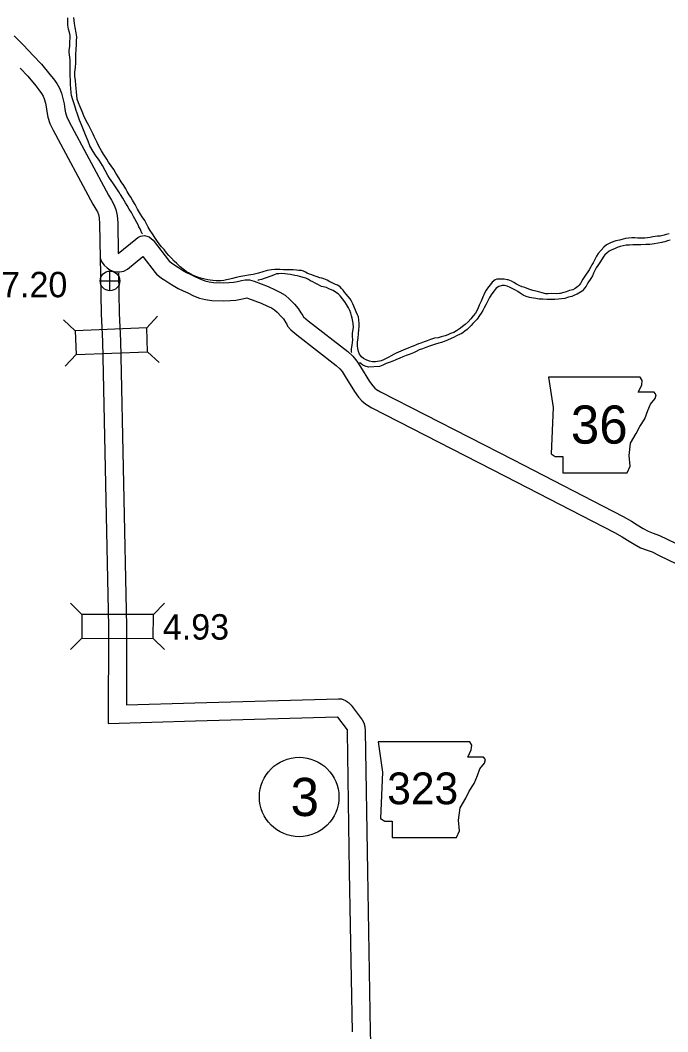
# Model space of a CAD drawing. Extents: x -939622 to -934222, y 1383701 to 1385301.
# Drawn here: x -936285.2 to -936253, y 1384484.4 to 1384534.8 of the extents above; entities that cross this region are included whole.
import ezdxf

# ---------------------------------------------------------------- set-up
doc = ezdxf.new("R2010")
doc.units = 0
for name, color, linetype in [('10', 7, 'Continuous'), ('20', 7, 'Continuous'), ('21', 7, 'Continuous'), ('25', 7, 'Continuous'), ('26', 7, 'Continuous'), ('27', 7, 'Continuous'), ('9', 7, 'Continuous')]:
    doc.layers.add(name, color=color, linetype=linetype)

msp = doc.modelspace()

# ---------------------------------------------------------------- linework, layer by layer
at = {"layer": '10'}
for points in [[(-936285.526, 1384534.038), (-936285.08, 1384533.582), (-936284.57, 1384533.041)], [(-936284.573, 1384533.044), (-936284.164, 1384532.618), (-936283.745, 1384532.106), (-936283.572, 1384531.883), (-936283.408, 1384531.657), (-936283.272, 1384531.427), (-936283.173, 1384531.173), (-936283.097, 1384530.903), (-936283.038, 1384530.648), (-936283.006, 1384530.383), (-936282.974, 1384530.194), (-936282.908, 1384529.999), (-936282.786, 1384529.739), (-936280.82, 1384526.086), (-936280.672, 1384525.843), (-936280.558, 1384525.629), (-936280.46, 1384525.374), (-936280.402, 1384525.086), (-936280.368, 1384524.714), (-936280.35, 1384523.196), (-936280.342, 1384523.189), (-936280.34, 1384523.188), (-936279.466, 1384523.908), (-936279.371, 1384523.99), (-936279.231, 1384524.05), (-936279.04, 1384524.085), (-936278.797, 1384524.018), (-936278.609, 1384523.847), (-936277.785, 1384522.789), (-936277.777, 1384522.777), (-936277.762, 1384522.765), (-936277.693, 1384522.722), (-936277.529, 1384522.612), (-936277.335, 1384522.486), (-936277.136, 1384522.359), (-936276.939, 1384522.243), (-936276.725, 1384522.141), (-936276.495, 1384522.03), (-936276.226, 1384521.904), (-936276.029, 1384521.825), (-936275.819, 1384521.775), (-936275.595, 1384521.742), (-936275.12, 1384521.73), (-936274.807, 1384521.739), (-936274.603, 1384521.758), (-936274.401, 1384521.79), (-936274.202, 1384521.835), (-936274.021, 1384521.875), (-936273.803, 1384521.869), (-936273.572, 1384521.802), (-936272.878, 1384521.543), (-936272.525, 1384521.379), (-936272.288, 1384521.267), (-936272.019, 1384521.106), (-936271.806, 1384520.911), (-936271.558, 1384520.664), (-936271.376, 1384520.451), (-936271.245, 1384520.234), (-936271.149, 1384520.105), (-936271.124, 1384520.043)], [(-936285.222, 1384532.421), (-936284.838, 1384532.021), (-936284.449, 1384531.544), (-936284.292, 1384531.343), (-936284.162, 1384531.163), (-936284.084, 1384531.031), (-936284.027, 1384530.887), (-936283.969, 1384530.68), (-936283.926, 1384530.491), (-936283.896, 1384530.253), (-936283.849, 1384529.974), (-936283.745, 1384529.664), (-936283.591, 1384529.335), (-936281.601, 1384525.638), (-936281.454, 1384525.396), (-936281.378, 1384525.254), (-936281.327, 1384525.122), (-936281.294, 1384524.956), (-936281.267, 1384524.667), (-936281.247, 1384522.946), (-936281.161, 1384522.755), (-936281.039, 1384522.597), (-936280.894, 1384522.478), (-936280.753, 1384522.375), (-936280.53, 1384522.271), (-936280.262, 1384522.265), (-936280.056, 1384522.31), (-936279.881, 1384522.401), (-936279.115, 1384523.031), (-936278.501, 1384522.243), (-936278.435, 1384522.154), (-936278.289, 1384522.033), (-936278.18, 1384521.965), (-936278.026, 1384521.862), (-936277.823, 1384521.729), (-936277.606, 1384521.591), (-936277.362, 1384521.448), (-936277.114, 1384521.329), (-936276.881, 1384521.218), (-936276.584, 1384521.078), (-936276.301, 1384520.965), (-936275.99, 1384520.891), (-936275.672, 1384520.844), (-936275.118, 1384520.83), (-936274.753, 1384520.84), (-936274.49, 1384520.865), (-936274.231, 1384520.906), (-936274.006, 1384520.957), (-936273.94, 1384520.971), (-936273.854, 1384520.947), (-936273.225, 1384520.712), (-936272.908, 1384520.565), (-936272.713, 1384520.472), (-936272.56, 1384520.381), (-936272.428, 1384520.26), (-936272.218, 1384520.051), (-936272.108, 1384519.923), (-936271.993, 1384519.732), (-936271.94, 1384519.66), (-936271.902, 1384519.566)], [(-936281.248, 1384523.036), (-936281.186, 1384520.184), (-936281.132, 1384518.802), (-936280.824, 1384504.606), (-936280.838, 1384499.779), (-936276.499, 1384499.898), (-936269.427, 1384500.095), (-936269.426, 1384500.094), (-936268.941, 1384499.459), (-936268.939, 1384499.455), (-936268.931, 1384499.358), (-936268.831, 1384492.386), (-936268.688, 1384484.416)], [(-936280.33, 1384522.202), (-936280.287, 1384520.211), (-936280.233, 1384518.829), (-936279.924, 1384504.615), (-936279.935, 1384500.704), (-936276.524, 1384500.797), (-936269.369, 1384500.997), (-936269.225, 1384500.994), (-936269.021, 1384500.924), (-936268.865, 1384500.81), (-936268.74, 1384500.678), (-936268.19, 1384499.958), (-936268.099, 1384499.799), (-936268.05, 1384499.617), (-936268.032, 1384499.402), (-936267.931, 1384492.401), (-936267.789, 1384484.432)], [(-936271.124, 1384520.041), (-936271.114, 1384520.029), (-936270.875, 1384519.829), (-936268.906, 1384518.299), (-936268.647, 1384518.064), (-936268.459, 1384517.828), (-936268.279, 1384517.544), (-936267.826, 1384516.817), (-936267.662, 1384516.599), (-936267.562, 1384516.482), (-936267.477, 1384516.404), (-936267.278, 1384516.288), (-936260.659, 1384512.9), (-936255.19, 1384510.081), (-936254.775, 1384509.85), (-936254.496, 1384509.671), (-936254.187, 1384509.479), (-936253.947, 1384509.35), (-936253.685, 1384509.254), (-936253.385, 1384509.142), (-936252.999, 1384508.951), (-936249.506, 1384507.269)], [(-936271.902, 1384519.566), (-936271.749, 1384519.387), (-936271.44, 1384519.128), (-936269.485, 1384517.609), (-936269.306, 1384517.447), (-936269.194, 1384517.307), (-936269.041, 1384517.065), (-936268.569, 1384516.307), (-936268.365, 1384516.036), (-936268.21, 1384515.854), (-936268.012, 1384515.675), (-936267.71, 1384515.498), (-936261.071, 1384512.1), (-936255.615, 1384509.288), (-936255.237, 1384509.078), (-936254.977, 1384508.911), (-936254.639, 1384508.7), (-936254.317, 1384508.526), (-936253.997, 1384508.41), (-936253.744, 1384508.315), (-936253.393, 1384508.142), (-936249.967, 1384506.492)], [(-936267.789, 1384484.438), (-936267.619, 1384478.861)]]:
    msp.add_lwpolyline(points, dxfattribs=at)
at = {"layer": '20'}
for p, q in [((-936278.925, 1384519.478), (-936278.387, 1384520.06)), ((-936282.486, 1384519.339), (-936283.068, 1384519.877)), ((-936282.44, 1384518.152), (-936282.978, 1384517.571)), ((-936278.879, 1384518.291), (-936278.297, 1384517.753)), ((-936282.154, 1384505.209), (-936282.713, 1384505.771)), ((-936278.59, 1384505.199), (-936278.029, 1384505.758)), ((-936282.157, 1384504.021), (-936282.719, 1384503.463)), ((-936278.594, 1384504.011), (-936278.035, 1384503.45))]:
    msp.add_line(p, q, dxfattribs=at)
for points in [[(-936282.44, 1384518.152), (-936278.879, 1384518.291), (-936278.925, 1384519.478), (-936282.486, 1384519.339)], [(-936282.157, 1384504.021), (-936278.594, 1384504.011), (-936278.59, 1384505.199), (-936282.154, 1384505.209)]]:
    msp.add_lwpolyline(points, close=True, dxfattribs=at)
at = {"layer": '21'}
for points in [[(-936258.902, 1384517.033), (-936258.674, 1384515.511), (-936258.776, 1384513.202), (-936258.573, 1384513.075), (-936258.192, 1384513.075), (-936258.192, 1384512.263), (-936254.994, 1384512.263), (-936254.842, 1384512.592), (-936254.893, 1384513.125), (-936254.817, 1384513.734), (-936254.538, 1384514.217), (-936254.36, 1384514.572), (-936254.106, 1384514.953), (-936253.954, 1384515.359), (-936253.827, 1384515.688), (-936253.599, 1384515.968), (-936253.548, 1384516.145), (-936253.649, 1384516.272), (-936254.436, 1384516.272), (-936254.258, 1384516.627), (-936254.233, 1384516.856), (-936254.338, 1384517.031)], [(-936267.398, 1384498.862), (-936267.17, 1384497.34), (-936267.271, 1384495.03), (-936267.068, 1384494.903), (-936266.687, 1384494.903), (-936266.687, 1384494.091), (-936263.49, 1384494.091), (-936263.338, 1384494.421), (-936263.388, 1384494.954), (-936263.312, 1384495.563), (-936263.033, 1384496.045), (-936262.856, 1384496.401), (-936262.602, 1384496.781), (-936262.449, 1384497.187), (-936262.323, 1384497.517), (-936262.094, 1384497.796), (-936262.043, 1384497.974), (-936262.145, 1384498.101), (-936262.932, 1384498.101), (-936262.754, 1384498.456), (-936262.729, 1384498.685), (-936262.834, 1384498.86)]]:
    msp.add_lwpolyline(points, close=True, dxfattribs=at)
at = {"layer": '26'}
for p, q in [((-936280.752, 1384521.334), (-936280.752, 1384522.309)), ((-936281.239, 1384521.821), (-936280.264, 1384521.821))]:
    msp.add_line(p, q, dxfattribs=at)
msp.add_circle((-936280.752, 1384521.821), 0.487, dxfattribs=at)
at = {"layer": '27'}
msp.add_circle((-936271.329, 1384496.111), 1.98, dxfattribs=at)
at = {"layer": '9'}
for points in [[(-936280.513, 1384526.562), (-936280.613, 1384526.709), (-936280.691, 1384526.818), (-936280.776, 1384526.945), (-936280.858, 1384527.079), (-936281.133, 1384527.567), (-936281.299, 1384527.836), (-936281.475, 1384528.09), (-936281.597, 1384528.267), (-936281.749, 1384528.555), (-936281.84, 1384528.781), (-936281.94, 1384529.022), (-936282.078, 1384529.349), (-936282.175, 1384529.602), (-936282.278, 1384529.834), (-936282.395, 1384530.17), (-936282.444, 1384530.31), (-936282.511, 1384530.543), (-936282.56, 1384530.689), (-936282.61, 1384530.847), (-936282.669, 1384531.053), (-936282.688, 1384531.182), (-936282.71, 1384531.428), (-936282.718, 1384531.59), (-936282.727, 1384531.804), (-936282.737, 1384532.068), (-936282.743, 1384532.17), (-936282.74, 1384532.387), (-936282.731, 1384532.496), (-936282.736, 1384532.664), (-936282.74, 1384532.811), (-936282.747, 1384532.971), (-936282.772, 1384533.087), (-936282.79, 1384533.207), (-936282.781, 1384533.31), (-936282.759, 1384533.494), (-936282.745, 1384533.747), (-936282.741, 1384533.907), (-936282.742, 1384534.048), (-936282.764, 1384534.192), (-936282.813, 1384534.362), (-936282.852, 1384534.562), (-936282.86, 1384534.743), (-936282.856, 1384534.92)], [(-936277.932, 1384523.226), (-936278.053, 1384523.382), (-936278.183, 1384523.525), (-936278.299, 1384523.667), (-936278.386, 1384523.782), (-936278.518, 1384523.982), (-936278.637, 1384524.166), (-936278.744, 1384524.337), (-936278.845, 1384524.506), (-936278.927, 1384524.669), (-936279.022, 1384524.832), (-936279.156, 1384525.011), (-936279.238, 1384525.148), (-936279.389, 1384525.393), (-936279.501, 1384525.634), (-936279.539, 1384525.681), (-936279.637, 1384525.849), (-936279.722, 1384525.988), (-936279.8, 1384526.11), (-936279.889, 1384526.282), (-936279.965, 1384526.412), (-936280.065, 1384526.571), (-936280.188, 1384526.763), (-936280.317, 1384526.961), (-936280.458, 1384527.195), (-936280.565, 1384527.364), (-936280.697, 1384527.552), (-936280.819, 1384527.739), (-936280.916, 1384527.889), (-936281.083, 1384528.14), (-936281.174, 1384528.3), (-936281.304, 1384528.525), (-936281.39, 1384528.718), (-936281.534, 1384529.012), (-936281.597, 1384529.134), (-936281.668, 1384529.297), (-936281.804, 1384529.555), (-936281.94, 1384529.798), (-936282.059, 1384530.05), (-936282.143, 1384530.268), (-936282.233, 1384530.494), (-936282.314, 1384530.684), (-936282.385, 1384530.881), (-936282.422, 1384531.238), (-936282.456, 1384531.568), (-936282.474, 1384531.799), (-936282.496, 1384532.027), (-936282.498, 1384532.216), (-936282.472, 1384532.455), (-936282.457, 1384532.684), (-936282.448, 1384532.901), (-936282.453, 1384533.093), (-936282.443, 1384533.367), (-936282.428, 1384533.575), (-936282.418, 1384533.765), (-936282.412, 1384533.973), (-936282.439, 1384534.183), (-936282.488, 1384534.437), (-936282.521, 1384534.647), (-936282.55, 1384534.938)], [(-936279.134, 1384524.16), (-936279.164, 1384524.202), (-936279.215, 1384524.33), (-936279.254, 1384524.407), (-936279.311, 1384524.514), (-936279.349, 1384524.606), (-936279.41, 1384524.736), (-936279.511, 1384524.908), (-936279.578, 1384525.033), (-936279.682, 1384525.222), (-936279.795, 1384525.397), (-936279.899, 1384525.583), (-936279.978, 1384525.716), (-936280.12, 1384525.938), (-936280.227, 1384526.125), (-936280.24, 1384526.148), (-936280.309, 1384526.252), (-936280.418, 1384526.405), (-936280.513, 1384526.562)], [(-936252.89, 1384524.171), (-936253.039, 1384524.127), (-936253.149, 1384524.1), (-936253.34, 1384524.053), (-936253.478, 1384524.046), (-936253.595, 1384524.027), (-936253.702, 1384524.009), (-936253.837, 1384523.981), (-936253.974, 1384523.96), (-936254.109, 1384523.95), (-936254.283, 1384523.942), (-936254.449, 1384523.946), (-936254.608, 1384523.96), (-936254.758, 1384523.961), (-936254.917, 1384523.951), (-936255.064, 1384523.926), (-936255.189, 1384523.901), (-936255.374, 1384523.848), (-936255.55, 1384523.813), (-936255.777, 1384523.74), (-936256.011, 1384523.622), (-936256.154, 1384523.507), (-936256.279, 1384523.356), (-936256.428, 1384523.183), (-936256.508, 1384523.058), (-936256.608, 1384522.85), (-936256.679, 1384522.725), (-936256.749, 1384522.627), (-936256.791, 1384522.529), (-936256.883, 1384522.373), (-936256.949, 1384522.278), (-936257.036, 1384522.158), (-936257.191, 1384521.913), (-936257.257, 1384521.788), (-936257.314, 1384521.69), (-936257.372, 1384521.61), (-936257.439, 1384521.545), (-936257.586, 1384521.438), (-936257.699, 1384521.381), (-936257.854, 1384521.335), (-936258.032, 1384521.272), (-936258.14, 1384521.239), (-936258.328, 1384521.201), (-936258.355, 1384521.197), (-936258.51, 1384521.181), (-936258.745, 1384521.186), (-936258.931, 1384521.181), (-936259.045, 1384521.184), (-936259.217, 1384521.221), (-936259.46, 1384521.292), (-936259.681, 1384521.349), (-936259.781, 1384521.376), (-936259.881, 1384521.41), (-936260.093, 1384521.488), (-936260.217, 1384521.524), (-936260.339, 1384521.574), (-936260.498, 1384521.666), (-936260.638, 1384521.746), (-936260.751, 1384521.803), (-936260.918, 1384521.868), (-936260.966, 1384521.882), (-936261.111, 1384521.899), (-936261.247, 1384521.913), (-936261.358, 1384521.913), (-936261.475, 1384521.9), (-936261.567, 1384521.871), (-936261.717, 1384521.764), (-936261.798, 1384521.641), (-936261.891, 1384521.524), (-936262.009, 1384521.353), (-936262.081, 1384521.242), (-936262.197, 1384520.977), (-936262.261, 1384520.816), (-936262.355, 1384520.618), (-936262.428, 1384520.429), (-936262.545, 1384520.212), (-936262.652, 1384520.074), (-936262.771, 1384519.929), (-936262.902, 1384519.778), (-936263.066, 1384519.647), (-936263.184, 1384519.55), (-936263.299, 1384519.472), (-936263.496, 1384519.328), (-936263.623, 1384519.258), (-936263.793, 1384519.193), (-936263.92, 1384519.129), (-936264.051, 1384519.083), (-936264.26, 1384519.032), (-936264.409, 1384518.989), (-936264.579, 1384518.96), (-936264.779, 1384518.897), (-936264.954, 1384518.835), (-936265.1, 1384518.783), (-936265.261, 1384518.727), (-936265.383, 1384518.685), (-936265.499, 1384518.642)], [(-936252.851, 1384523.856), (-936252.982, 1384523.813), (-936253.107, 1384523.773), (-936253.214, 1384523.746), (-936253.256, 1384523.739), (-936253.447, 1384523.701), (-936253.633, 1384523.668), (-936253.851, 1384523.641), (-936254.058, 1384523.632), (-936254.301, 1384523.625), (-936254.496, 1384523.62), (-936254.707, 1384523.617), (-936254.866, 1384523.609), (-936255.036, 1384523.593), (-936255.195, 1384523.57), (-936255.338, 1384523.542), (-936255.493, 1384523.489), (-936255.626, 1384523.422), (-936255.751, 1384523.365), (-936255.882, 1384523.307), (-936256.008, 1384523.201), (-936256.093, 1384523.123), (-936256.157, 1384523.052)], [(-936265.499, 1384518.642), (-936265.644, 1384518.575), (-936265.751, 1384518.53), (-936265.905, 1384518.474), (-936266.033, 1384518.423), (-936266.155, 1384518.371), (-936266.374, 1384518.275), (-936266.499, 1384518.217), (-936266.6, 1384518.166), (-936266.741, 1384518.081), (-936266.857, 1384518.017), (-936266.99, 1384517.953), (-936267.121, 1384517.893), (-936267.245, 1384517.844), (-936267.32, 1384517.818), (-936267.523, 1384517.791), (-936267.671, 1384517.79), (-936267.828, 1384517.818), (-936267.955, 1384517.878), (-936268.12, 1384517.961), (-936268.221, 1384518.042), (-936268.33, 1384518.165), (-936268.379, 1384518.305), (-936268.41, 1384518.458), (-936268.429, 1384518.593), (-936268.422, 1384518.785), (-936268.395, 1384518.973), (-936268.371, 1384519.208), (-936268.349, 1384519.383), (-936268.333, 1384519.543), (-936268.337, 1384519.697), (-936268.35, 1384519.859), (-936268.367, 1384520.03), (-936268.415, 1384520.134), (-936268.489, 1384520.288), (-936268.599, 1384520.568), (-936268.647, 1384520.684), (-936268.714, 1384520.811), (-936268.78, 1384520.921), (-936268.883, 1384521.05), (-936268.979, 1384521.165), (-936269.066, 1384521.265), (-936269.143, 1384521.353), (-936269.212, 1384521.444), (-936269.286, 1384521.526), (-936269.421, 1384521.604), (-936269.521, 1384521.646), (-936269.679, 1384521.72), (-936269.795, 1384521.78), (-936269.936, 1384521.863), (-936270.1, 1384521.921), (-936270.203, 1384521.949), (-936270.3, 1384521.979), (-936270.433, 1384522.023), (-936270.573, 1384522.074), (-936270.694, 1384522.118), (-936270.815, 1384522.163), (-936270.928, 1384522.208), (-936271.013, 1384522.251), (-936271.108, 1384522.299), (-936271.211, 1384522.332), (-936271.34, 1384522.347), (-936271.461, 1384522.352), (-936271.623, 1384522.375), (-936271.845, 1384522.366), (-936272.107, 1384522.376), (-936272.288, 1384522.389), (-936272.42, 1384522.394), (-936272.543, 1384522.397), (-936272.705, 1384522.374), (-936272.914, 1384522.332), (-936273.14, 1384522.269), (-936273.358, 1384522.202), (-936273.617, 1384522.135), (-936273.845, 1384522.104), (-936274.039, 1384522.081), (-936274.23, 1384522.036), (-936274.463, 1384521.982), (-936274.645, 1384521.94), (-936274.786, 1384521.909), (-936274.944, 1384521.872), (-936275.084, 1384521.844), (-936275.237, 1384521.83), (-936275.339, 1384521.828), (-936275.459, 1384521.827), (-936275.622, 1384521.838), (-936275.766, 1384521.855), (-936275.884, 1384521.875), (-936276.029, 1384521.91), (-936276.295, 1384521.969), (-936276.432, 1384522.022), (-936276.557, 1384522.079), (-936276.675, 1384522.13), (-936276.834, 1384522.216), (-936276.95, 1384522.291), (-936277.254, 1384522.514), (-936277.43, 1384522.692), (-936277.55, 1384522.809), (-936277.683, 1384522.947), (-936277.814, 1384523.094), (-936277.932, 1384523.226)], [(-936256.157, 1384523.052), (-936256.358, 1384522.743), (-936256.453, 1384522.596), (-936256.531, 1384522.467), (-936256.605, 1384522.339), (-936256.671, 1384522.201), (-936256.721, 1384522.065), (-936256.795, 1384521.933), (-936256.949, 1384521.724), (-936257.037, 1384521.553), (-936257.106, 1384521.452), (-936257.211, 1384521.326), (-936257.231, 1384521.313), (-936257.388, 1384521.206), (-936257.482, 1384521.159), (-936257.616, 1384521.107), (-936257.744, 1384521.049), (-936257.911, 1384521.008), (-936258.095, 1384520.952), (-936258.26, 1384520.926), (-936258.416, 1384520.907), (-936258.587, 1384520.896), (-936258.782, 1384520.893), (-936258.974, 1384520.894), (-936259.191, 1384520.903), (-936259.365, 1384520.919), (-936259.531, 1384520.938), (-936259.661, 1384520.959), (-936259.848, 1384520.998), (-936260.012, 1384521.048), (-936260.164, 1384521.116), (-936260.313, 1384521.202), (-936260.433, 1384521.286), (-936260.546, 1384521.364), (-936260.677, 1384521.432), (-936260.82, 1384521.495), (-936260.972, 1384521.553), (-936261.099, 1384521.589), (-936261.217, 1384521.592), (-936261.377, 1384521.539), (-936261.51, 1384521.454), (-936261.609, 1384521.328), (-936261.728, 1384521.18), (-936261.842, 1384520.99), (-936261.948, 1384520.795), (-936262.028, 1384520.63), (-936262.116, 1384520.471), (-936262.185, 1384520.34), (-936262.259, 1384520.205), (-936262.34, 1384520.089), (-936262.467, 1384519.917), (-936262.569, 1384519.799), (-936262.674, 1384519.697), (-936262.759, 1384519.607), (-936262.855, 1384519.505), (-936262.952, 1384519.406), (-936263.069, 1384519.316), (-936263.163, 1384519.247), (-936263.225, 1384519.206), (-936263.335, 1384519.146), (-936263.489, 1384519.078), (-936263.608, 1384519.021), (-936263.946, 1384518.861), (-936264.109, 1384518.805), (-936264.237, 1384518.756), (-936264.377, 1384518.716), (-936264.532, 1384518.67), (-936264.684, 1384518.623), (-936264.839, 1384518.574), (-936265.017, 1384518.506), (-936265.189, 1384518.441), (-936265.347, 1384518.382), (-936265.495, 1384518.309), (-936265.64, 1384518.241), (-936265.804, 1384518.176), (-936265.997, 1384518.096), (-936266.166, 1384518.031), (-936266.312, 1384517.979), (-936266.511, 1384517.892), (-936266.662, 1384517.824), (-936266.847, 1384517.759), (-936266.995, 1384517.707), (-936267.158, 1384517.624), (-936267.318, 1384517.556), (-936267.874, 1384517.531), (-936268.04, 1384517.572), (-936268.164, 1384517.622), (-936268.235, 1384517.681), (-936268.312, 1384517.745), (-936268.321, 1384517.75)], [(-936268.635, 1384519.718), (-936268.681, 1384519.961), (-936268.714, 1384520.086), (-936268.757, 1384520.22), (-936268.797, 1384520.352), (-936268.864, 1384520.485), (-936268.973, 1384520.638), (-936269.061, 1384520.786), (-936269.167, 1384520.922), (-936269.292, 1384521.072), (-936269.388, 1384521.183), (-936269.513, 1384521.264), (-936269.642, 1384521.342), (-936269.848, 1384521.429), (-936269.968, 1384521.498), (-936270.212, 1384521.545), (-936270.404, 1384521.636), (-936270.532, 1384521.702), (-936270.654, 1384521.767), (-936270.764, 1384521.83), (-936270.871, 1384521.897), (-936271.002, 1384521.959), (-936271.123, 1384521.995), (-936271.301, 1384522.035), (-936271.422, 1384522.065), (-936271.552, 1384522.091), (-936271.755, 1384522.139), (-936271.912, 1384522.162), (-936272.05, 1384522.179), (-936272.192, 1384522.187), (-936272.339, 1384522.177), (-936272.459, 1384522.165), (-936272.607, 1384522.103), (-936272.917, 1384521.998), (-936273.071, 1384521.94), (-936273.208, 1384521.894), (-936273.369, 1384521.85), (-936273.389, 1384521.845)], [(-936268.707, 1384518.231), (-936268.718, 1384518.278), (-936268.722, 1384518.431), (-936268.688, 1384518.622), (-936268.654, 1384518.89), (-936268.676, 1384519.052), (-936268.666, 1384519.224), (-936268.614, 1384519.502), (-936268.635, 1384519.718)]]:
    msp.add_lwpolyline(points, dxfattribs=at)

# ---------------------------------------------------------------- texts
at = {"layer": '21'}
for s, height, p in [('36', 1.9008, (-936257.793, 1384513.713)), ('323', 1.584, (-936266.941, 1384495.747))]:
    msp.add_text(s, height=height, dxfattribs=at).set_placement(p)
at = {"layer": '25'}
for s, p in [('7.20', (-936286.176, 1384521.004)), ('4.93', (-936278.118, 1384503.95))]:
    msp.add_text(s, height=1.2672, dxfattribs=at).set_placement(p)
at = {"layer": '27'}
msp.add_text('3', height=1.901, dxfattribs=at).set_placement((-936271.754, 1384495.161))

doc.saveas('drawing.dxf')
